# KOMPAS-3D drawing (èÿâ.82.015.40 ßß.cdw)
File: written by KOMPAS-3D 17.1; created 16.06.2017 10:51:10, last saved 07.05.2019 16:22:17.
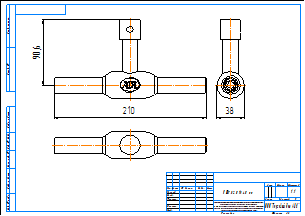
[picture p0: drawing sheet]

Sheet 1: A3, landscape

Title block, sheet 1: name: КШГ.82.015.40 сс; material: Внимание! Данный продукт является объектом авторского права ООО «Торговый Дом АДЛ». / Запрещается изменение, копирование, распространение / (в том числе путем копирования на другие сайты и ресурсы в Интернете) / или любое иное использование информации и объектов без предварительного / согласия правообладателя (ООО «Торговый Дом АДЛ»).; scale: 1:1; sheets: 1; organisation: ООО "Торговый дом АДЛ"; sheet format: A3; stored path: C:\Users\tra\Desktop\2д чертежи\Шаровые краны БИВАЛ\КШ_Бивал_серия_82_85\KOMPAS 2D\КШГ.82.015.40 сс.cdw

Views: Спереди 1, Проекционный вид 2, Проекционный вид 3
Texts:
  Klimkovich
  ADL
Dimensions and other numbers on the sheet: 210; 90,6; 38; 1:1; 1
